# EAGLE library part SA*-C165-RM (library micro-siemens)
MICROPROCESSOR/PERIPHERAL DEVICE
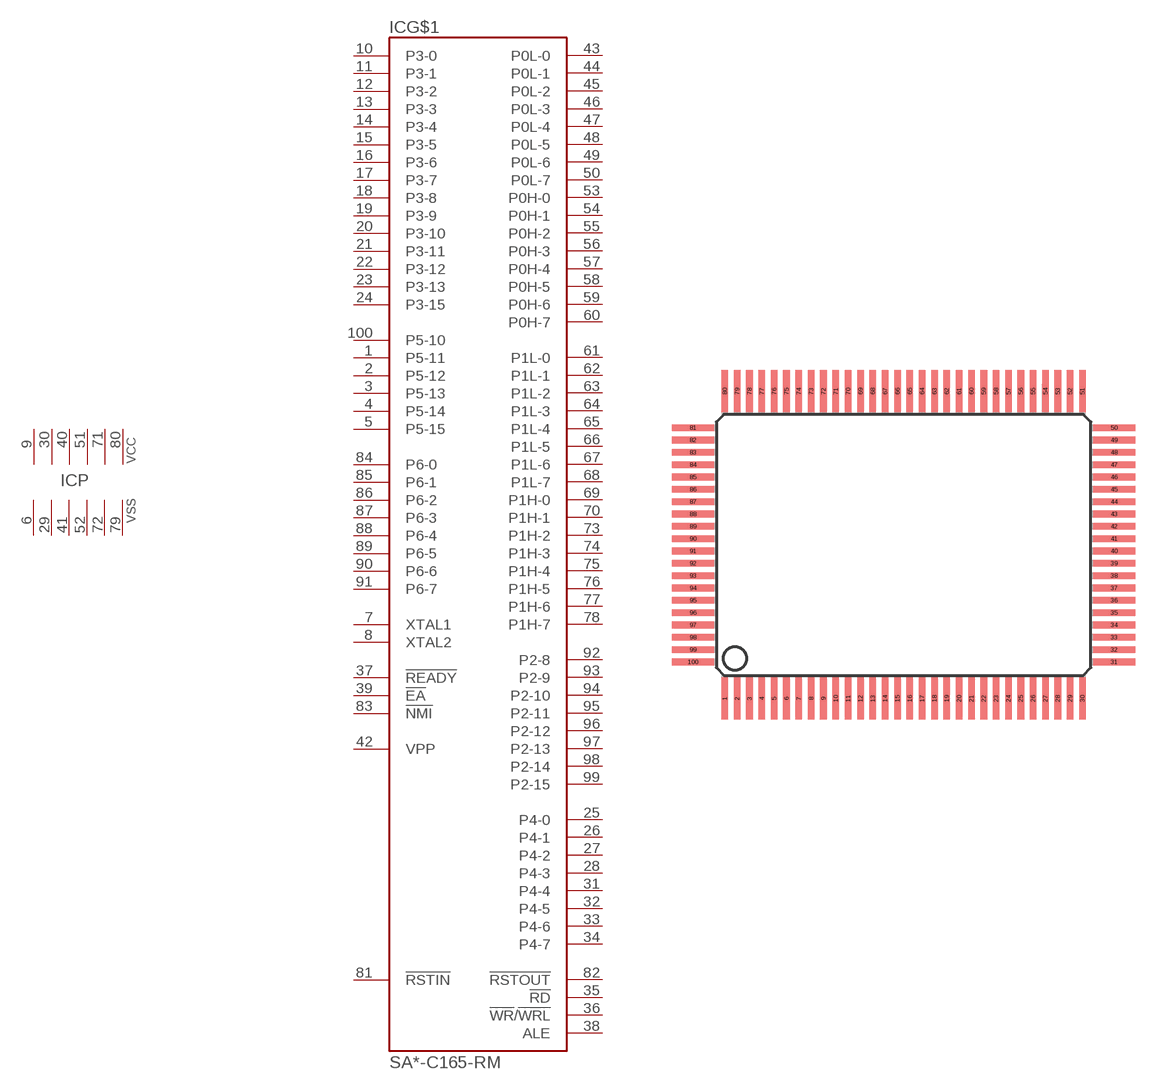
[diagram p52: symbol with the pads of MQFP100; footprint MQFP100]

Designator prefix IC; gates G$1=C165-1 P=6_VCCVSS

## SAB-C165-RM (OC_FARNELL: unknown; OC_NEWARK: unknown), SAK-C165-RM (OC_FARNELL: unknown; OC_NEWARK: unknown)  [MQFP100]
1  G$1:P5-11  in
2  G$1:P5-12  in
3  G$1:P5-13  in
4  G$1:P5-14  in
5  G$1:P5-15  in
6  P:VSS  pwr
7  G$1:XTAL1  in
8  G$1:XTAL2  out
9  P:VCC  pwr
10  G$1:P3-0
11  G$1:P3-1
12  G$1:P3-2
13  G$1:P3-3
14  G$1:P3-4
15  G$1:P3-5
16  G$1:P3-6
17  G$1:P3-7
18  G$1:P3-8
19  G$1:P3-9
20  G$1:P3-10
21  G$1:P3-11
22  G$1:P3-12
23  G$1:P3-13
24  G$1:P3-15
25  G$1:P4-0
26  G$1:P4-1
27  G$1:P4-2
28  G$1:P4-3
29  P:VSS  pwr
30  P:VCC  pwr
31  G$1:P4-4
32  G$1:P4-5
33  G$1:P4-6
34  G$1:P4-7
35  G$1:!RD  out
36  G$1:!WR!/!WRL  out
37  G$1:!READY  in
38  G$1:ALE  out
39  G$1:!EA  in
40  P:VCC  pwr
41  P:VSS  pwr
42  G$1:VPP  pas
43  G$1:P0L-0
44  G$1:P0L-1
45  G$1:P0L-2
46  G$1:P0L-3
47  G$1:P0L-4
48  G$1:P0L-5
49  G$1:P0L-6
50  G$1:P0L-7
51  P:VCC  pwr
52  P:VSS  pwr
53  G$1:P0H-0
54  G$1:P0H-1
55  G$1:P0H-2
56  G$1:P0H-3
57  G$1:P0H-4
58  G$1:P0H-5
59  G$1:P0H-6
60  G$1:P0H-7
61  G$1:P1L-0
62  G$1:P1L-1
63  G$1:P1L-2
64  G$1:P1L-3
65  G$1:P1L-4
66  G$1:P1L-5
67  G$1:P1L-6
68  G$1:P1L-7
69  G$1:P1H-0
70  G$1:P1H-1
71  P:VCC  pwr
72  P:VSS  pwr
73  G$1:P1H-2
74  G$1:P1H-3
75  G$1:P1H-4
76  G$1:P1H-5
77  G$1:P1H-6
78  G$1:P1H-7
79  P:VSS  pwr
80  P:VCC  pwr
81  G$1:!RSTIN  in
82  G$1:!RSTOUT  out
83  G$1:!NMI  in
84  G$1:P6-0
85  G$1:P6-1
86  G$1:P6-2
87  G$1:P6-3
88  G$1:P6-4
89  G$1:P6-5
90  G$1:P6-6
91  G$1:P6-7
92  G$1:P2-8
93  G$1:P2-9
94  G$1:P2-10
95  G$1:P2-11
96  G$1:P2-12
97  G$1:P2-13
98  G$1:P2-14
99  G$1:P2-15
100  G$1:P5-10  in

## Footprint MQFP100 (pad centres in mm)
Metric Quad Flat Pack
smd 0.35 x 2.2: 1 -9.425,-8.1; 2 -8.775,-8.1; 3 -8.125,-8.1; 4 -7.475,-8.1; 5 -6.825,-8.1; 6 -6.175,-8.1; 7 -5.525,-8.1; 8 -4.875,-8.1; 9 -4.225,-8.1; 10 -3.575,-8.1; 11 -2.925,-8.1; 12 -2.275,-8.1; 13 -1.625,-8.1; 14 -0.975,-8.1; 15 -0.325,-8.1; 16 0.325,-8.1; 17 0.975,-8.1; 18 1.625,-8.1; 19 2.275,-8.1; 20 2.925,-8.1; 21 3.575,-8.1; 22 4.225,-8.1; 23 4.875,-8.1; 24 5.525,-8.1; 25 6.175,-8.1; 26 6.825,-8.1; 27 7.475,-8.1; 28 8.125,-8.1; 29 8.775,-8.1; 30 9.425,-8.1; 51 9.425,8.1; 52 8.775,8.1; 53 8.125,8.1; 54 7.475,8.1; 55 6.825,8.1; 56 6.175,8.1; 57 5.525,8.1; 58 4.875,8.1; 59 4.225,8.1; 60 3.575,8.1; 61 2.925,8.1; 62 2.275,8.1; 63 1.625,8.1; 64 0.975,8.1; 65 0.325,8.1; 66 -0.325,8.1; 67 -0.975,8.1; 68 -1.625,8.1; 69 -2.275,8.1; 70 -2.925,8.1; 71 -3.575,8.1; 72 -4.225,8.1; 73 -4.875,8.1; 74 -5.525,8.1; 75 -6.175,8.1; 76 -6.825,8.1; 77 -7.475,8.1; 78 -8.125,8.1; 79 -8.775,8.1; 80 -9.425,8.1
smd 2.2 x 0.35: 31 11.1,-6.175; 32 11.1,-5.525; 33 11.1,-4.875; 34 11.1,-4.225; 35 11.1,-3.575; 36 11.1,-2.925; 37 11.1,-2.275; 38 11.1,-1.625; 39 11.1,-0.975; 40 11.1,-0.325; 41 11.1,0.325; 42 11.1,0.975; 43 11.1,1.625; 44 11.1,2.275; 45 11.1,2.925; 46 11.1,3.575; 47 11.1,4.225; 48 11.1,4.875; 49 11.1,5.525; 50 11.1,6.175; 81 -11.1,6.175; 82 -11.1,5.525; 83 -11.1,4.875; 84 -11.1,4.225; 85 -11.1,3.575; 86 -11.1,2.925; 87 -11.1,2.275; 88 -11.1,1.625; 89 -11.1,0.975; 90 -11.1,0.325; 91 -11.1,-0.325; 92 -11.1,-0.975; 93 -11.1,-1.625; 94 -11.1,-2.275; 95 -11.1,-2.925; 96 -11.1,-3.575; 97 -11.1,-4.225; 98 -11.1,-4.875; 99 -11.1,-5.525; 100 -11.1,-6.175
